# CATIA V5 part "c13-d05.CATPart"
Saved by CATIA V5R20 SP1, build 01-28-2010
Part number: Part1
Bounding box of the stored display mesh (mm): x -62.5 to 62.5, y -75 to 75, z 0 to 20
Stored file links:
  D:\v5_r20\psrt_files_downloaded\c13-catia-v5r20-prt\c13-catia-v5r20-figr-13-18 & 20\c13-d05.CATPart
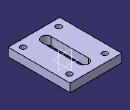
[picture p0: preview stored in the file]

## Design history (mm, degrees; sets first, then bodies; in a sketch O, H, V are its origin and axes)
Body1 (main body)
  Sketch1 on xy-plane, origin (0, 0, 0), H (1, 0, 0), V (0, 1, 0)
    line L1 (62.5, 75) -> (62.5, -75)
    line L2 (62.5, -75) -> (-62.5, -75)
    line L3 (-62.5, -75) -> (-62.5, 75)
    line L4 (-62.5, 75) -> (62.5, 75)
    length L1 = 150
    length L2 = 125
    vertical: L1 V, L3 V
    horizontal: L2 H, L4 H
    equidistance: L1 L3 O, L2 L4 O
  Pad1: profile Sketch1, direction (0, 0, 1), length 20
  Sketch2 on face of Pad1, origin (0, 0, 20), H (1, 0, 0), V (0, 1, 0)
    construction line L1 (0, 45) -> (0, -45)
    point P1 (0, 45)
    line L2 (12, 45) -> (12, -45)
    line L3 (-12, -45) -> (-12, 45)
    arc A1 centre (0, -45) radius 12 from (12, -45) to (-12, -45) cw
    arc A2 centre (0, 45) radius 12 from (-12, 45) to (12, 45) cw
    length L1 = 90
    radius A2 = 12
    coincidence: P1 V
    vertical: L1 V
    tangency: A1 L2, A2 L2, A1 L3, A2 L3
    parallelism: L1 L2
    midpoint: O L1
  Pocket1: profile Sketch2, direction (0, 0, -1), through (limit type 3)
  Sketch3 on face of Pad1, origin (38.7626, -18.4621, 20), H (1, 0, 0), V (0, 1, 0)
    point P1 (5.7374, -38.5379)
    reference projected line E1 (-101.2626, -56.5379) -> (23.7374, -56.5379) from edge [face of Pad1 | face of Pad1]
    reference projected line E2 (23.7374, -56.5379) -> (23.7374, 93.4621) from edge [face of Pad1 | face of Pad1]
    distance P1 E1 = 18
    distance P1 E2 = 18
  Hole1: placed by Sketch3, at (44.5, -57, 20) direction (0, 0, -1), diameter 13, through (limit type 3)
  RectPattern1: of Hole1, direction 1 instances 2, spacing 86, along edge [face of Pad1 | face of Pad1] reversed, direction 2 instances 2, spacing 112, along edge [face of Pad1 | face of Pad1]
